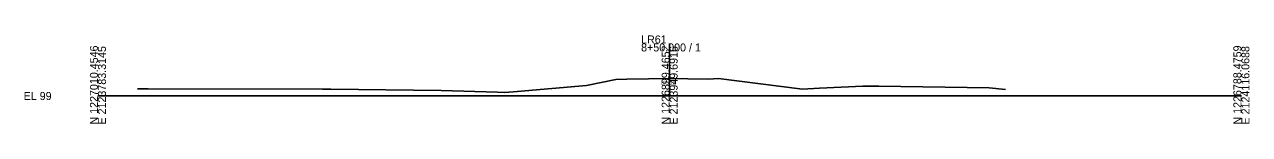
# Model space of a CAD drawing. Extents: x -26 to 1403, y -10 to 9574.
# Drawn here: x -25.7 to 402.8, y 8490.3 to 8521.3 of the extents above; entities that cross this region are included whole.
import ezdxf

# ---------------------------------------------------------------- set-up
doc = ezdxf.new("R2010")
doc.units = 0
for name, color, linetype in [('XS_CELL', 7, 'Continuous'), ('XS_X_GROUND', 7, 'Continuous'), ('XS_X_GROUND_TX', 7, 'Continuous')]:
    doc.layers.add(name, color=color, linetype=linetype)

msp = doc.modelspace()

# ---------------------------------------------------------------- linework, layer by layer
at = {"layer": 'XS_CELL'}
for p, q in [((200, 8500), (200, 8518.41)), ((0, 8500), (200, 8500)), ((200, 8500), (400, 8500))]:
    msp.add_line(p, q, dxfattribs=at)
at = {"layer": 'XS_X_GROUND'}
for p, q in [((13.85, 8502.52), (14.26, 8502.52)), ((14.26, 8502.52), (16.03, 8502.5)), ((16.03, 8502.5), (17.57, 8502.47)), ((17.57, 8502.47), (78.61, 8502.43)), ((78.61, 8502.43), (80.41, 8502.44)), ((80.41, 8502.44), (81.43, 8502.41)), ((81.43, 8502.41), (120.07, 8501.9)), ((146.6, 8501.53), (170.85, 8503.72)), ((170.85, 8503.72), (181.16, 8505.79)), ((181.16, 8505.79), (185.05, 8505.92)), ((185.05, 8505.92), (192.65, 8506.04)), ((192.65, 8506.04), (199.42, 8506.14)), ((199.42, 8506.14), (200, 8506.12)), ((200, 8506.12), (206.36, 8505.99)), ((206.36, 8505.99), (213.6, 8505.84)), ((213.6, 8505.84), (217.07, 8506.08)), ((217.07, 8506.08), (245.5, 8502.49)), ((245.5, 8502.49), (246.33, 8502.36)), ((246.33, 8502.36), (252.44, 8502.69)), ((252.44, 8502.69), (267.61, 8503.43)), ((267.61, 8503.43), (273.2, 8503.42)), ((273.2, 8503.42), (311.74, 8502.87)), ((311.74, 8502.87), (317.47, 8502.25)), ((120.07, 8501.9), (139.81, 8501.29)), ((139.81, 8501.29), (142.3, 8501.21)), ((142.3, 8501.21), (146.6, 8501.53))]:
    msp.add_line(p, q, dxfattribs=at)

# ---------------------------------------------------------------- texts
at = {"layer": 'XS_CELL'}
for s, p in [('LR61', (190, 8518.41)), ('8+50.000 / 1', (190, 8515.61)), ('EL 99', (-26, 8498.6))]:
    msp.add_text(s, height=2.8, dxfattribs=at).set_placement(p)
for s, p in [('N 1227010.4546', (0, 8490)), ('E 2123783.3145', (2.8, 8490)), ('N 1226899.4652', (200, 8490)), ('E 2123949.6916', (202.8, 8490)), ('N 1226788.4759', (400, 8490)), ('E 2124116.0688', (402.8, 8490))]:
    msp.add_text(s, height=2.8, rotation=90, dxfattribs=at).set_placement(p)
at = {"layer": 'XS_X_GROUND_TX'}
msp.add_text('105.12', height=1.25, rotation=360, dxfattribs=at).set_placement((196.76, 8504.06))

doc.saveas('drawing.dxf')
